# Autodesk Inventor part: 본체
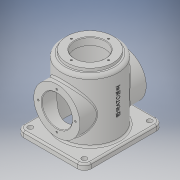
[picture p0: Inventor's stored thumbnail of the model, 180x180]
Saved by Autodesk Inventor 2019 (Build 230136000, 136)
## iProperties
Created: 2020-12
Part Number: 본체
Material: 일반
Document SubType Name: Modeling
Designer: jun-1-3
Mass: 456.569 g
Surface Area: 1073.84 cm^2
Volume: 456.569 cm^3
Density: 1 g/cm^3
Appearance: 기본값
Author: jun-1-3
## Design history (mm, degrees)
sketch "스케치1"
  geometry: L1 (60, 70)-(-60, 70); L2 (-60, 70)-(-60, -70); L3 (-60, -70)-(60, -70); L4 (60, -70)-(60, 70); L5 (60, 70)-(-60, -70); L6 (-60, 70)-(60, -70); 1 further point
  constraints: 12 end point, 2 midpoint, 2 parallel, 1 horizontal, 1 perpendicular
  dimensions: "d0" = 120 distance of L3.end L2.end; "d1" = 140 distance of L2.end L1.end
extrude "돌출1" new body sketch "스케치1" distance "d2" = 10; taper "d3" = 0 deg
sketch "스케치2"
  geometry: C1 r 50 at (0, 0); 1 further point
  constraints: 1 centre point, 1 coincident
  dimensions: "d4" = 100 diameter of C1
extrude "돌출2" join sketch "스케치2" distance "d5" = 120; taper "d6" = 0 deg
sketch "스케치3"
  geometry: C1 r 41 at (0, 0); 1 further point
  constraints: 1 centre point, 1 coincident
  dimensions: "d7" = 82 diameter of C1
extrude "돌출3" join sketch "스케치3" distance "d8" = 5; taper "d9" = 0 deg
node "작업 평면1"
sketch "스케치4"
  geometry: L1 (-60, 0)-(60, 0) reference; C1 r 41 at (0, 60); 2 further points
  constraints: 1 centre point, 1 midpoint, 1 vertical alignment
  dimensions: "d11" = 82 diameter of C1; "d12" = 60 distance from line of L1 C1.centre
extrude "돌출4" join sketch "스케치4" stored distance "d13" = 5; taper "d14" = 0 deg
sketch "스케치5" dims "d15" = 66
  geometry: C1 r 41 at (0, 0) reference; 3 further points
  constraints: 2 vertical alignment, 3 other
hole "구멍1" sketch "스케치5" at (0, 33) diameter "d16" = 3.242; stored, may be unused: countersink angle "d20" = 90 deg, drill point angle "d22" = 118 deg; dims "d17" = 8, "d18" = 4, "d19" = 2, "d21" = 10
sketch "스케치6"
  geometry: C1 r 41 at (0, 0) reference; 2 further points
  constraints: 1 coincident
hole "구멍2" sketch "스케치6" at (0, 0) diameter "d26" = 54; stored, may be unused: countersink angle "d30" = 90 deg, drill point angle "d32" = 118 deg; dims "d27" = 8, "d28" = 4, "d29" = 2, "d31" = 10
sketch "스케치7" dims "d33" = 66
  geometry: 3 further points
  constraints: 2 horizontal alignment, 1 coincident, 2 other
hole "구멍3" sketch "스케치7" at (-33, 0) diameter "d34" = 3.242; stored, may be unused: countersink angle "d38" = 90 deg, drill point angle "d40" = 118 deg; dims "d35" = 8, "d36" = 4, "d37" = 2, "d39" = 10
sketch "스케치8"
  geometry: C1 r 41 at (0, 0) reference; 2 further points
  constraints: 1 coincident
hole "구멍4" sketch "스케치8" at (0, 0) diameter "d44" = 54; stored, may be unused: countersink angle "d48" = 90 deg, drill point angle "d50" = 118 deg; dims "d45" = 8, "d46" = 4, "d47" = 2, "d49" = 10
sketch "스케치9"
  geometry: C1 r 42 at (0, 0); 1 further point
  constraints: 1 centre point, 1 coincident
  dimensions: "d51" = 84 diameter of C1
extrude "돌출5" cut sketch "스케치9" distance "d52" = 112; taper "d53" = 0 deg
fillet "모깎기1" dims "d54" = 12
sketch "스케치10"
  geometry: A1 r 12 centre (-48, 58) between (-48, 70) and (-60, 58) reference; A2 r 12 centre (-48, -58) between (-60, -58) and (-48, -70) reference; A3 r 12 centre (48, -58) between (48, -70) and (60, -58) reference; A4 r 12 centre (48, 58) between (60, 58) and (48, 70) reference; 5 further points
  constraints: 4 coincident
hole "구멍5" sketch "스케치10" at (-48, 58), (-48, -58), (48, -58), (48, 58) diameter "d55" = 9; stored, may be unused: countersink angle "d59" = 90 deg, drill point angle "d61" = 118 deg; dims "d56" = 8, "d57" = 4, "d58" = 2, "d60" = 10
node "작업 평면2"
sketch "스케치11"
  geometry: L1 (0, 58)-(0, -58) reference; L2 (45.795, 3.868)-(95.57, 3.868); L3 (95.57, 3.868)-(95.57, -3.337); L4 (95.57, -3.337)-(45.795, -3.337); L5 (45.795, -3.337)-(45.795, 3.868); 3 further points
  constraints: 1 horizontal alignment, 1 midpoint, 2 other
  dimensions: "d63" = 70 distance from line of L1 point (70, 0)
feature "엠보싱1" sketch "스케치11" dims "d0" = 120, "d1" = 140, "d64" = 0.5, "d65" = 0
fillet "모깎기2" dims "d66" = 3
fillet "모깎기3" dims "d67" = 6
chamfer "모따기1" distance "d68" = 1; stored, may be unused: second distance "d69" = 2, angle "d70" = 45 deg
fillet "모깎기4" dims "d71" = 3
node "솔리드1"
pattern_circular "원형 패턴1" dims angle "d24" = 360 deg
mirror "미러1"
pattern_circular "원형 패턴2" dims angle "d42" = 360 deg
other parameters: "d10" = 59
